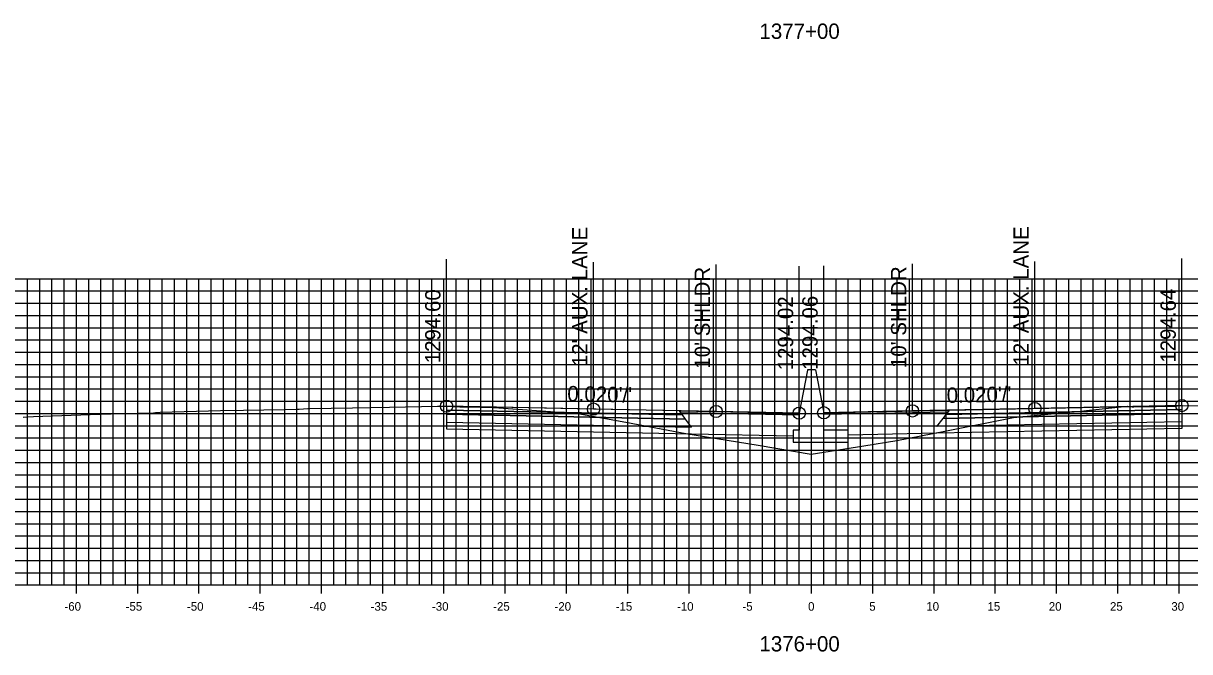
# Model space of a CAD drawing. Extents: x 674939 to 678919, y 750652 to 765176.
# Drawn here: x 678674.2 to 678769.4, y 754892.1 to 754943.4 of the extents above; entities that cross this region are included whole.
import ezdxf

# ---------------------------------------------------------------- set-up
doc = ezdxf.new("R2010")
doc.units = 0
for name, color, linetype in [('R_Alt Surface', 7, 'Continuous'), ('R_Axis', 7, 'Continuous'), ('R_Axis Annot', 7, 'Continuous'), ('R_Exist Surface', 7, 'Continuous'), ('R_Fin Surface', 7, 'Continuous'), ('R_Grid', 7, 'Continuous'), ('R_No Plot', 7, 'Continuous'), ('R_Proposed Road', 7, 'Continuous'), ('R_Xsect Elev', 7, 'Continuous'), ('R_Xsect Slope', 7, 'Continuous')]:
    doc.layers.add(name, color=color, linetype=linetype)

msp = doc.modelspace()

# ---------------------------------------------------------------- linework, layer by layer
at = {"layer": 'R_Alt Surface'}
for points in [[(678708.745, 754911.818), (678708.745, 754911.488), (678728.245, 754911.098), (678727.995, 754911.433)], [(678708.745, 754911.488), (678708.745, 754910.828), (678728.745, 754910.428), (678728.245, 754911.098)], [(678768.768, 754911.535), (678768.768, 754910.875), (678748.768, 754910.475), (678749.268, 754911.145)], [(678768.768, 754911.865), (678768.768, 754911.535), (678749.268, 754911.145), (678749.518, 754911.48)]]:
    msp.add_lwpolyline(points, close=True, dxfattribs=at)
for points in [[(678708.745, 754910.828), (678708.745, 754910.288), (678728.745, 754909.888), (678737.033, 754909.722)], [(678768.768, 754910.875), (678768.768, 754910.335), (678748.768, 754909.935), (678741.533, 754909.79)]]:
    msp.add_lwpolyline(points, dxfattribs=at)
at = {"layer": 'R_Axis'}
for p, q in [((678678.533, 754896.851), (678678.533, 754898.251)), ((678683.533, 754896.851), (678683.533, 754898.251)), ((678688.533, 754896.851), (678688.533, 754898.251)), ((678693.533, 754896.851), (678693.533, 754898.251)), ((678698.533, 754896.851), (678698.533, 754898.251)), ((678703.533, 754896.851), (678703.533, 754898.251)), ((678708.533, 754896.851), (678708.533, 754898.251)), ((678713.533, 754896.851), (678713.533, 754898.251)), ((678718.533, 754896.851), (678718.533, 754898.251)), ((678723.533, 754896.851), (678723.533, 754898.251)), ((678728.533, 754896.851), (678728.533, 754898.251)), ((678733.533, 754896.851), (678733.533, 754898.251)), ((678738.533, 754896.851), (678738.533, 754898.251)), ((678743.533, 754896.851), (678743.533, 754898.251)), ((678748.533, 754896.851), (678748.533, 754898.251)), ((678753.533, 754896.851), (678753.533, 754898.251)), ((678758.533, 754896.851), (678758.533, 754898.251)), ((678763.533, 754896.851), (678763.533, 754898.251)), ((678768.533, 754896.851), (678768.533, 754898.251)), ((678638.533, 754897.551), (678838.533, 754897.551))]:
    msp.add_line(p, q, dxfattribs=at)
at = {"layer": 'R_Exist Surface'}
msp.add_lwpolyline([(678674.19, 754911.248), (678674.52, 754911.271), (678675.014, 754911.298), (678679.657, 754911.463), (678681.359, 754911.525), (678683.535, 754911.572), (678683.92, 754911.578), (678684.645, 754911.588), (678684.983, 754911.621), (678685.114, 754911.628), (678685.212, 754911.639), (678685.355, 754911.646), (678690.291, 754911.781), (678692.155, 754911.83), (678695.495, 754911.875), (678696.536, 754911.895), (678696.7, 754911.894), (678697.426, 754911.944), (678697.591, 754911.96), (678701.077, 754912.018), (678704.088, 754912.072), (678708.01, 754912.139), (678708.659, 754912.15), (678708.745, 754912.148), (678708.823, 754912.149), (678709.839, 754912.095), (678710.3, 754912.082), (678711.027, 754912.092), (678711.574, 754912.076), (678712.583, 754912.03), (678712.637, 754912.029), (678716.853, 754911.734), (678719.464, 754911.544), (678723.368, 754910.84), (678728.264, 754909.929), (678734.186, 754908.955), (678738.508, 754908.217), (678742.804, 754908.913), (678745.509, 754909.355), (678749.422, 754910.114), (678755.009, 754911.225), (678758.944, 754911.595), (678760.334, 754911.718), (678760.992, 754911.789), (678764.325, 754912.153), (678764.359, 754912.141), (678764.55, 754912.106), (678764.696, 754912.094), (678764.842, 754912.105), (678765.134, 754912.114), (678766.657, 754912.133), (678767.462, 754912.138), (678768.223, 754912.148), (678768.42, 754912.166), (678768.768, 754912.195), (678768.791, 754912.196), (678768.823, 754912.199), (678770.579, 754912.17)], dxfattribs=at)
at = {"layer": 'R_Fin Surface'}
for points in [[(678737.533, 754911.572), (678730.745, 754911.708), (678720.745, 754911.908), (678708.745, 754912.148)], [(678768.768, 754912.195), (678756.768, 754911.955), (678746.768, 754911.755), (678739.533, 754911.61)]]:
    msp.add_lwpolyline(points, dxfattribs=at)
for points in [[(678708.745, 754912.148), (678708.745, 754911.818), (678727.995, 754911.433), (678727.745, 754911.768)], [(678768.768, 754912.195), (678768.768, 754911.865), (678749.518, 754911.48), (678749.768, 754911.815)], [(678727.745, 754911.768), (678737.533, 754911.572), (678737.537, 754911.414), (678727.865, 754911.608)], [(678749.649, 754911.655), (678739.533, 754911.453), (678739.533, 754911.61), (678749.768, 754911.815)]]:
    msp.add_lwpolyline(points, close=True, dxfattribs=at)
at = {"layer": 'R_Grid'}
for p, q in [((678638.533, 754922.551), (678838.533, 754922.551)), ((678674.533, 754897.551), (678674.533, 754922.551)), ((678675.533, 754897.551), (678675.533, 754922.551)), ((678676.533, 754897.551), (678676.533, 754922.551)), ((678677.533, 754897.551), (678677.533, 754922.551)), ((678678.533, 754897.551), (678678.533, 754922.551)), ((678679.533, 754897.551), (678679.533, 754922.551)), ((678680.533, 754897.551), (678680.533, 754922.551)), ((678681.533, 754897.551), (678681.533, 754922.551)), ((678682.533, 754897.551), (678682.533, 754922.551)), ((678683.533, 754897.551), (678683.533, 754922.551)), ((678684.533, 754897.551), (678684.533, 754922.551)), ((678685.533, 754897.551), (678685.533, 754922.551)), ((678686.533, 754897.551), (678686.533, 754922.551)), ((678687.533, 754897.551), (678687.533, 754922.551)), ((678688.533, 754897.551), (678688.533, 754922.551)), ((678689.533, 754897.551), (678689.533, 754922.551)), ((678690.533, 754897.551), (678690.533, 754922.551)), ((678691.533, 754897.551), (678691.533, 754922.551)), ((678692.533, 754897.551), (678692.533, 754922.551)), ((678693.533, 754897.551), (678693.533, 754922.551)), ((678694.533, 754897.551), (678694.533, 754922.551)), ((678695.533, 754897.551), (678695.533, 754922.551)), ((678696.533, 754897.551), (678696.533, 754922.551)), ((678697.533, 754897.551), (678697.533, 754922.551)), ((678698.533, 754897.551), (678698.533, 754922.551)), ((678699.533, 754897.551), (678699.533, 754922.551)), ((678700.533, 754897.551), (678700.533, 754922.551)), ((678701.533, 754897.551), (678701.533, 754922.551)), ((678702.533, 754897.551), (678702.533, 754922.551)), ((678703.533, 754897.551), (678703.533, 754922.551)), ((678704.533, 754897.551), (678704.533, 754922.551)), ((678705.533, 754897.551), (678705.533, 754922.551)), ((678706.533, 754897.551), (678706.533, 754922.551)), ((678707.533, 754897.551), (678707.533, 754922.551)), ((678708.533, 754897.551), (678708.533, 754922.551)), ((678709.533, 754897.551), (678709.533, 754922.551)), ((678710.533, 754897.551), (678710.533, 754922.551)), ((678711.533, 754897.551), (678711.533, 754922.551)), ((678712.533, 754897.551), (678712.533, 754922.551)), ((678713.533, 754897.551), (678713.533, 754922.551)), ((678714.533, 754897.551), (678714.533, 754922.551)), ((678715.533, 754897.551), (678715.533, 754922.551)), ((678716.533, 754897.551), (678716.533, 754922.551)), ((678717.533, 754897.551), (678717.533, 754922.551)), ((678718.533, 754897.551), (678718.533, 754922.551)), ((678719.533, 754897.551), (678719.533, 754922.551)), ((678720.533, 754897.551), (678720.533, 754922.551)), ((678721.533, 754897.551), (678721.533, 754922.551)), ((678722.533, 754897.551), (678722.533, 754922.551)), ((678723.533, 754897.551), (678723.533, 754922.551)), ((678724.533, 754897.551), (678724.533, 754922.551)), ((678725.533, 754897.551), (678725.533, 754922.551)), ((678726.533, 754897.551), (678726.533, 754922.551)), ((678727.533, 754897.551), (678727.533, 754922.551)), ((678728.533, 754897.551), (678728.533, 754922.551)), ((678729.533, 754897.551), (678729.533, 754922.551)), ((678730.533, 754897.551), (678730.533, 754922.551)), ((678731.533, 754897.551), (678731.533, 754922.551)), ((678732.533, 754897.551), (678732.533, 754922.551)), ((678733.533, 754897.551), (678733.533, 754922.551)), ((678734.533, 754897.551), (678734.533, 754922.551)), ((678735.533, 754897.551), (678735.533, 754922.551)), ((678736.533, 754897.551), (678736.533, 754922.551)), ((678737.533, 754897.551), (678737.533, 754922.551)), ((678738.533, 754897.551), (678738.533, 754922.551)), ((678739.533, 754897.551), (678739.533, 754922.551)), ((678740.533, 754897.551), (678740.533, 754922.551)), ((678741.533, 754897.551), (678741.533, 754922.551)), ((678742.533, 754897.551), (678742.533, 754922.551)), ((678743.533, 754897.551), (678743.533, 754922.551)), ((678744.533, 754897.551), (678744.533, 754922.551)), ((678745.533, 754897.551), (678745.533, 754922.551)), ((678746.533, 754897.551), (678746.533, 754922.551)), ((678747.533, 754897.551), (678747.533, 754922.551)), ((678748.533, 754897.551), (678748.533, 754922.551)), ((678749.533, 754897.551), (678749.533, 754922.551)), ((678750.533, 754897.551), (678750.533, 754922.551)), ((678751.533, 754897.551), (678751.533, 754922.551)), ((678752.533, 754897.551), (678752.533, 754922.551)), ((678753.533, 754897.551), (678753.533, 754922.551)), ((678754.533, 754897.551), (678754.533, 754922.551)), ((678755.533, 754897.551), (678755.533, 754922.551)), ((678756.533, 754897.551), (678756.533, 754922.551)), ((678757.533, 754897.551), (678757.533, 754922.551)), ((678758.533, 754897.551), (678758.533, 754922.551)), ((678759.533, 754897.551), (678759.533, 754922.551)), ((678760.533, 754897.551), (678760.533, 754922.551)), ((678761.533, 754897.551), (678761.533, 754922.551)), ((678762.533, 754897.551), (678762.533, 754922.551)), ((678763.533, 754897.551), (678763.533, 754922.551)), ((678764.533, 754897.551), (678764.533, 754922.551)), ((678765.533, 754897.551), (678765.533, 754922.551)), ((678766.533, 754897.551), (678766.533, 754922.551)), ((678767.533, 754897.551), (678767.533, 754922.551)), ((678768.533, 754897.551), (678768.533, 754922.551)), ((678638.533, 754921.551), (678838.533, 754921.551)), ((678638.533, 754920.551), (678838.533, 754920.551)), ((678638.533, 754919.551), (678838.533, 754919.551)), ((678638.533, 754918.551), (678838.533, 754918.551)), ((678638.533, 754917.551), (678838.533, 754917.551)), ((678638.533, 754916.551), (678838.533, 754916.551)), ((678638.533, 754915.551), (678838.533, 754915.551)), ((678638.533, 754914.551), (678838.533, 754914.551)), ((678638.533, 754913.551), (678838.533, 754913.551)), ((678638.533, 754912.551), (678838.533, 754912.551)), ((678638.533, 754911.551), (678838.533, 754911.551)), ((678638.533, 754910.551), (678838.533, 754910.551)), ((678638.533, 754909.551), (678838.533, 754909.551)), ((678638.533, 754908.551), (678838.533, 754908.551)), ((678638.533, 754907.551), (678838.533, 754907.551)), ((678638.533, 754906.551), (678838.533, 754906.551)), ((678638.533, 754905.551), (678838.533, 754905.551)), ((678638.533, 754904.551), (678838.533, 754904.551)), ((678638.533, 754903.551), (678838.533, 754903.551)), ((678638.533, 754902.551), (678838.533, 754902.551)), ((678638.533, 754901.551), (678838.533, 754901.551)), ((678638.533, 754900.551), (678838.533, 754900.551)), ((678638.533, 754899.551), (678838.533, 754899.551)), ((678638.533, 754898.551), (678838.533, 754898.551)), ((678638.533, 754897.551), (678838.533, 754897.551))]:
    msp.add_line(p, q, dxfattribs=at)
at = {"layer": 'R_No Plot'}
for centre in [(678708.745, 754912.148), (678720.745, 754911.908), (678730.745, 754911.708), (678737.533, 754911.572), (678739.533, 754911.61), (678746.768, 754911.755), (678756.768, 754911.955), (678768.768, 754912.195)]:
    msp.add_circle(centre, 0.5, dxfattribs=at)
at = {"layer": 'R_Proposed Road'}
for points in [[(678738.203, 754915.072), (678737.533, 754911.572)], [(678738.863, 754915.11), (678738.863, 754915.11), (678738.203, 754915.11), (678738.203, 754915.072)], [(678738.863, 754915.11), (678739.533, 754911.61)], [(678737.533, 754911.572), (678737.533, 754910.197), (678737.033, 754910.197), (678737.033, 754909.197), (678741.533, 754909.197), (678741.533, 754910.197), (678739.533, 754910.197), (678739.533, 754911.61)]]:
    msp.add_lwpolyline(points, dxfattribs=at)
at = {"layer": 'R_Xsect Elev'}
for p, q in [((678708.745, 754912.148), (678708.745, 754924.148)), ((678720.745, 754911.908), (678720.745, 754923.908)), ((678730.745, 754911.708), (678730.745, 754923.708)), ((678737.533, 754911.572), (678737.533, 754923.572)), ((678739.533, 754911.61), (678739.533, 754923.61)), ((678746.768, 754911.755), (678746.768, 754923.755)), ((678756.768, 754911.955), (678756.768, 754923.955)), ((678768.768, 754912.195), (678768.768, 754924.195))]:
    msp.add_line(p, q, dxfattribs=at)

# ---------------------------------------------------------------- texts
at = {"layer": 'R_Axis Annot'}
for s, height, p in [('1377+00', 1.25, (678734.281, 754942.126)), ('-60', 0.7, (678677.552, 754895.451)), ('-55', 0.7, (678682.546, 754895.451)), ('-50', 0.7, (678687.552, 754895.451)), ('-45', 0.7, (678692.546, 754895.451)), ('-40', 0.7, (678697.552, 754895.451)), ('-35', 0.7, (678702.546, 754895.451)), ('-30', 0.7, (678707.552, 754895.451)), ('-25', 0.7, (678712.546, 754895.451)), ('-20', 0.7, (678717.552, 754895.451)), ('-15', 0.7, (678722.546, 754895.451)), ('-10', 0.7, (678727.552, 754895.451)), ('-5', 0.7, (678732.896, 754895.451)), ('0', 0.7, (678738.252, 754895.451)), ('5', 0.7, (678743.246, 754895.451)), ('10', 0.7, (678747.902, 754895.451)), ('15', 0.7, (678752.896, 754895.451)), ('20', 0.7, (678757.902, 754895.451)), ('25', 0.7, (678762.896, 754895.451)), ('30', 0.7, (678767.902, 754895.451)), ('1376+00', 1.25, (678734.282, 754892.126))]:
    msp.add_text(s, height=height, dxfattribs=at).set_placement(p)
at = {"layer": 'R_Xsect Elev'}
for s, p in [("12' AUX. LANE", (678720.245, 754915.408)), ("12' AUX. LANE", (678756.268, 754915.455)), ("10' SHLDR", (678730.245, 754915.208)), ("10' SHLDR", (678746.268, 754915.255)), ('1294.60', (678708.245, 754915.648)), ('1294.64', (678768.268, 754915.695)), ('1294.02', (678737.033, 754915.072)), ('1294.06', (678739.033, 754915.11))]:
    msp.add_text(s, height=1.25, rotation=90, dxfattribs=at).set_placement(p)
at = {"layer": 'R_Xsect Slope'}
for rotation, p in [(358.85424, (678718.589, 754912.551)), (1.14576, (678749.577, 754912.411))]:
    msp.add_text("0.020'/'", height=1.25, rotation=rotation, dxfattribs=at).set_placement(p)

doc.saveas('drawing.dxf')
